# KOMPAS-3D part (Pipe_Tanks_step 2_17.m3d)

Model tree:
1. X Axis
2. Y Axis
3. Z Axis  (labels: Pipe Dn 50; Valve Dy 50)
     Òîëùèíà ñòåíêè 1 = 1

Referenced files in C:\Documents and Settings\kashirsky\Мои документы\Camtasia Studio\Pipelines3D\Tanks\: Tanks_step 2.a3d
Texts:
  Pipe Dn 50
  Steel ASTM A295
  Three Point Plane
  Plane at Angle
  Line and Point Plane
  Axis through Two Vertices
  Axis of Feature
  Axis of Conical Surface
  Axis through Edge
  Trim by Surface
  Trim by Sketch
  Feature with No History
  Intersection Axis of Two Planes
  Two Line Plane
  Line and Face Plane
  Bend by line
  Hole in sheet body
  Cut in sheet body
  Point in CM
  Linear Dimension from Line to Point
  Surface Finish Symbol
  Geometric Tolerance Symbol
  Leader #1
  Leader #2
  Leader #3
  Shape Deviations and Datum
  Node point number
  Mark of coordination axis
  Node point designation
  Mark/Reference designation with leader
  Mark/reference designation on line
  Mark/Reference designation without leader
  Valve Dy 50
  Plane of section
